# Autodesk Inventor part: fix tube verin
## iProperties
Shininess: 63.0
Length Units: 11269
Angle Units: 11279
Time Units: 11290
Mass Units: 11283
Length Display Precision: 3
Angle Display Precision: 2
Created: 2002-09
Part Number: fix tube verin
Material: Par défaut
Document SubType Name: Modélisation
Designer: Maison
Density: 0.0
Volumn: 0.0
Area: 0.0
PropertySet Name: Model Information
Control State: 0
Master: False
Checked Out: False
Author: Maison
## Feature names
1. Extrusion1
2. Congé2 [Fillet]
3. Extrusion4
4. Extrusion5
5. Perçage4 [Hole]
6. Perçage5 [Hole]
7. Extrusion7
